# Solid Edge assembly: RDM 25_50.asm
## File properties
Title: Zylinder
Author: ahadarics
Template: iso metric assembly.asm
Last saved by: ahadarics
Revision: 15
Application: Solid Edge
Username: ahadarics
Dokumentum tartalom típus: 1
Document Number: RDM 25/50
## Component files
Profilrohr.par
Kolbenstange.par
Kit_1.par
Kit_2.par
Mutter_1.par
Mutter_2.par
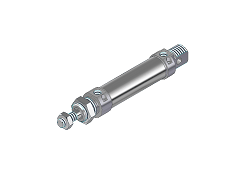
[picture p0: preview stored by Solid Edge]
